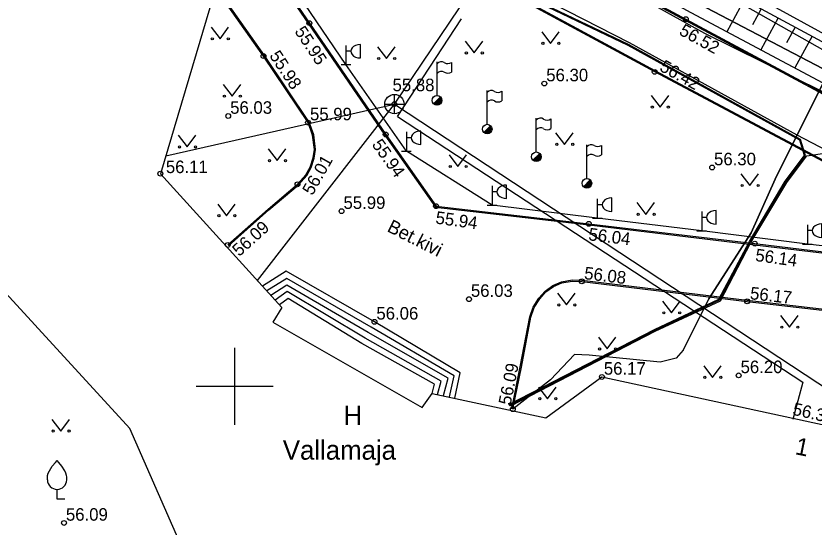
# Model space of a CAD drawing. Extents: x 542320 to 543602, y 6558748 to 6559969.
# Drawn here: x 543038.66 to 543080.07, y 6558892.7 to 6558919.22 of the extents above; entities that cross this region are included whole.
import ezdxf

# ---------------------------------------------------------------- set-up
doc = ezdxf.new("R2010")
doc.units = 0
for name, color, linetype in [('HALJASTUS', 7, 'Continuous'), ('HOONE', 7, 'Continuous'), ('HOONEDET', 7, 'Continuous'), ('KKAEV', 7, 'Continuous'), ('KORGUS-EH2000', 7, 'Continuous'), ('KTRASS', 7, 'Continuous'), ('MPKAABEL', 7, 'Continuous'), ('MPOHULIIN', 7, 'Continuous'), ('PIIR', 7, 'Continuous'), ('POST', 7, 'Continuous'), ('PUU', 7, 'Continuous'), ('RAJATIS', 7, 'Continuous'), ('RELJEEF', 7, 'Continuous'), ('SITRASS', 7, 'Continuous'), ('TEE', 7, 'Continuous'), ('VORK', 7, 'Continuous'), ('VTRASS', 7, 'Continuous')]:
    doc.layers.add(name, color=color, linetype=linetype)

# ---------------------------------------------------------------- blocks, each defined once
blk = doc.blocks.new('VKORIS')
for p, q in [((0, 4), (0, -4)), ((-4, 0), (4, 0))]:
    blk.add_line(p, q)
blk = doc.blocks.new('KAABVA')
for p, q in [((0, 2), (0, 0)), ((1.5, 0.693), (1.5, 2.093))]:
    blk.add_line(p, q)
for points in [[(0.5, 1.393), (0, 1.393)], [(-0.5, 0), (0.5, 0)]]:
    blk.add_lwpolyline(points)
blk.add_ellipse((1.5, 1.393), major_axis=(1, 0), ratio=0.7, start_param=1.570796, end_param=4.712389)
blk = doc.blocks.new('PLPOST')
blk.add_line((-0.354, -0.353), (0.353, 0.354))
blk.add_circle((0, 0), 0.5)
for radius, start, end in [(0.45, 224.85406, 45.03563), (0.4, 224.84272, 45.04698), (0.35, 224.82813, 45.06157), (0.3, 224.80867, 45.08103), (0.25, 224.78144, 45.10826), (0.2, 224.74058, 45.14911), (0.15, 224.67249, 45.2172), (0.1, 224.53632, 45.35338), (0.05, 224.12776, 45.76193)]:
    blk.add_arc((0, 0), radius, start, end)
blk = doc.blocks.new('LIPP')
for p, q in [((0, 0.5), (0, 4)), ((1.506, 3.938), (1.506, 2.938))]:
    blk.add_line(p, q)
for centre, radius, start, end in [((0.446, 3.431), 0.576, 57.89407, 140.73656), ((1.114, 4.496), 0.682, 237.89407, 305.02189), ((0.446, 2.431), 0.576, 57.89407, 140.73656), ((1.114, 3.496), 0.682, 237.89407, 305.02189)]:
    blk.add_arc(centre, radius, start, end)
blk = doc.blocks.new('KAKAEV')
for p, q in [((0, -1), (0, 1)), ((-1, 0), (1, 0))]:
    blk.add_line(p, q)
blk.add_circle((0, 0), 1)
blk = doc.blocks.new('MURU')
for p, q in [((-0.927, 1.213), (0, 0)), ((0, 0), (0.891, 1.213))]:
    blk.add_line(p, q)
for centre in [(-0.802, 0), (0.856, 0)]:
    blk.add_circle(centre, 0.11)
blk = doc.blocks.new('RING02')
blk.add_circle((0, 0), 0.25)
blk = doc.blocks.new('VILJA1')
for p, q in [((0, 0), (0, 1)), ((0.8, 0), (0, 0))]:
    blk.add_line(p, q)
for points in [[(-1, 2), (-1, 2.3), (-0.98, 2.43), (-0.91, 2.69), (-0.79, 2.93), (-0.5, 3.4), (-0.18, 3.81), (0, 4)], [(1, 2), (1, 2.3), (0.98, 2.43), (0.91, 2.69), (0.79, 2.93), (0.5, 3.4), (0.18, 3.81), (0, 4)]]:
    blk.add_lwpolyline(points)
blk.add_arc((0, 2), 1, 180, 0)

msp = doc.modelspace()

# ---------------------------------------------------------------- linework, layer by layer
at = {"layer": 'HOONE'}
msp.add_lwpolyline([(543034.683, 6558908.573), (543039.145, 6558923.204), (543048.898, 6558920.298), (543046.148, 6558911.034), (543052.456, 6558904.09), (543051.993, 6558903.334), (543059.743, 6558898.897), (543060.252, 6558899.636), (543066.159, 6558898.365), (543069.065, 6558900.487), (543081.93, 6558897.713), (543079.788, 6558887.775), (543071.384, 6558889.615), (543068.481, 6558887.445), (543058.412, 6558889.575), (543048.599, 6558888.632), (543044.558, 6558897.817)], close=True, dxfattribs=at)
at = {"layer": 'HOONEDET'}
for points in [[(543061.428, 6558899.383), (543061.705, 6558900.698), (543057.26, 6558903.347), (543052.674, 6558905.983), (543051.446, 6558905.202)], [(543061.158, 6558899.446), (543061.396, 6558900.537), (543057.097, 6558903.067), (543052.709, 6558905.6), (543051.668, 6558904.958)], [(543060.843, 6558899.519), (543061.082, 6558900.415), (543056.933, 6558902.787), (543052.712, 6558905.253), (543051.888, 6558904.716)], [(543060.537, 6558899.577), (543060.727, 6558900.266), (543056.77, 6558902.507), (543052.727, 6558904.925), (543052.104, 6558904.478)], [(543060.252, 6558899.636), (543060.381, 6558900.116), (543056.607, 6558902.227), (543052.787, 6558904.55), (543052.326, 6558904.233)]]:
    msp.add_lwpolyline(points, dxfattribs=at)
at = {"layer": 'KTRASS'}
for points in [[(543046.435, 6558911.953), (543058.296, 6558914.646), (543066.44, 6558926.74)], [(543051.198, 6558905.487), (543058.296, 6558914.646), (543080.977, 6558899.722)]]:
    msp.add_lwpolyline(points, dxfattribs=at)
at = {"layer": 'MPKAABEL'}
msp.add_lwpolyline([(543081.761, 6558896.926), (543082.099, 6558896.873), (543082.395, 6558897.034), (543085.057, 6558906.769), (543079.727, 6558907.382), (543074.242, 6558908.071), (543068.825, 6558908.727), (543063.367, 6558909.397), (543058.921, 6558912.202), (543055.778, 6558916.692), (543052.723, 6558921.189), (543049.567, 6558925.65)], dxfattribs=at)
at = {"layer": 'MPOHULIIN'}
msp.add_lwpolyline([(543099.403, 6558906.806), (543072.616, 6558921.947), (543045.501, 6558937.03), (543017.777, 6558952.769), (543011.701, 6558956.054)], dxfattribs=at)
at = {"layer": 'PIIR'}
for points in [[(543133.64, 6558888.72), (543040.58, 6558937.38), (543035.44, 6558940.39), (542997.88, 6558962.4), (542987.35, 6558968.48), (542985.46, 6558965.33), (542959.34, 6558980.79), (542961.33, 6558984.1), (542942.14, 6558992.15), (542929.74, 6558997.94), (542900.76, 6559010.27), (542901.6, 6559029.9)], [(543035.44, 6558940.39), (543040.58, 6558937.38), (543133.64, 6558888.72), (543159.27, 6558882.37), (543180.35, 6558877.33), (543188.6, 6558877.87), (543138.85, 6558855), (543136.39, 6558853.9), (543124.53, 6558851.31), (543111.21, 6558848.45), (543108.75, 6558866.73), (543082.72, 6558864.15), (543047.4, 6558848.41), (543054.87, 6558832.91), (543045.52, 6558829.45), (543026.29, 6558871.02), (543014.78, 6558890.86), (543006.52, 6558905.62), (543035.44, 6558940.39)]]:
    msp.add_lwpolyline(points, dxfattribs=at)
at = {"layer": 'RELJEEF'}
for points in [[(543101.897, 6558904.434), (543099.403, 6558906.806), (543096.044, 6558909.437), (543087.206, 6558914.268), (543074.649, 6558921.041), (543062.51, 6558927.7), (543050.982, 6558934.283), (543039.149, 6558941.077)], [(543037.968, 6558939.072), (543049.987, 6558932.338), (543073.674, 6558919.4), (543086.307, 6558912.668), (543095.539, 6558907.795), (543101.897, 6558904.434)], [(543076.451, 6558920.069), (543075.551, 6558918.4)], [(543077.332, 6558919.594), (543076.883, 6558918.762)], [(543078.212, 6558919.119), (543077.316, 6558917.459)], [(543079.092, 6558918.645), (543078.645, 6558917.817)], [(543079.972, 6558918.17), (543079.081, 6558916.519)]]:
    msp.add_lwpolyline(points, dxfattribs=at)
at = {"layer": 'SITRASS'}
for points in [[(543005.218, 6558957.454), (543044.997, 6558934.01), (543059.196, 6558926.752), (543074.381, 6558918.33), (543088.205, 6558911.502)], [(543064.26, 6558899.01), (543071.81, 6558902.91), (543075.17, 6558904.48), (543076.76, 6558907.49), (543078.62, 6558910.61), (543079.63, 6558911.97), (543079.37, 6558912.8), (543070.45, 6558917.73), (543064, 6558920.82), (543057.14, 6558924.93), (543052.25, 6558927.86), (543046.19, 6558930.99), (543042.46, 6558932.62), (543041.21, 6558933.18), (543040.24, 6558933.33), (543036.74, 6558935.74), (543033.41, 6558937.8), (543027.38, 6558941.25), (543021.13, 6558945), (543014.59, 6558948.63), (543009.37, 6558951.53), (543004.894, 6558954.068)], [(543064.24, 6558899.05), (543071.79, 6558902.95), (543075.13, 6558904.52), (543076.72, 6558907.51), (543078.58, 6558910.64), (543079.57, 6558911.98), (543079.33, 6558912.77), (543070.43, 6558917.69), (543063.98, 6558920.78), (543057.11, 6558924.89), (543052.23, 6558927.82), (543046.17, 6558930.94), (543042.44, 6558932.57), (543041.2, 6558933.13), (543040.22, 6558933.28), (543036.71, 6558935.7), (543033.38, 6558937.76), (543027.35, 6558941.21), (543021.1, 6558944.96), (543014.57, 6558948.59), (543009.35, 6558951.49), (543004.955, 6558953.977)], [(543121.901, 6558892.876), (543114.85, 6558896.99), (543111.27, 6558898.1), (543100.18, 6558902.69), (543091.12, 6558906.8), (543079.2, 6558913.04), (543070.5, 6558917.82), (543064.13, 6558921.1), (543057.19, 6558925.02), (543052.3, 6558927.95), (543046.23, 6558931.08), (543041.478, 6558932.313)], [(543150.381, 6558900.817), (543149.118, 6558899.488), (543147.687, 6558899.611), (543141.92, 6558901.373), (543128.068, 6558907.732), (543119.398, 6558911.928), (543114.519, 6558913.803), (543110.489, 6558914.465), (543105.407, 6558916.546), (543094.307, 6558922.284), (543086.864, 6558926.326), (543085.516, 6558925.687), (543081.664, 6558918.001), (543078.063, 6558910.75), (543076.812, 6558907.966), (543074.612, 6558904.543), (543073.274, 6558901.882), (543072.923, 6558901.455), (543072.094, 6558901.248), (543068.398, 6558901.619), (543067.64, 6558901.649), (543066.401, 6558900.344), (543064.442, 6558898.816)], [(543073.274, 6558901.882), (543074.612, 6558904.543), (543076.812, 6558907.966), (543078.063, 6558910.75), (543081.664, 6558918.001), (543085.516, 6558925.687)], [(543064.33, 6558898.99), (543071.83, 6558902.87), (543075.21, 6558904.44), (543076.8, 6558907.47), (543078.66, 6558910.58), (543079.69, 6558911.96), (543080.74, 6558912.11), (543085.83, 6558909.45), (543091.08, 6558906.71), (543100.42, 6558902.47), (543106.04, 6558900.15), (543110.07, 6558898.37), (543111.55, 6558895.04), (543112.38, 6558892.93), (543113.811, 6558888.962)]]:
    msp.add_lwpolyline(points, dxfattribs=at)
at = {"layer": 'TEE'}
for points in [[(543100.939, 6558907.078), (543096.605, 6558909.676), (543087.4, 6558914.549), (543074.818, 6558921.463), (543062.815, 6558928.334), (543051.193, 6558934.777), (543039.337, 6558941.411)], [(543037.628, 6558938.816), (543049.652, 6558932.038), (543061.266, 6558925.532), (543073.39, 6558918.997), (543086.032, 6558912.226), (543093.141, 6558908.472), (543101.872, 6558904.379), (543104.96, 6558903.002), (543104.998, 6558903.893), (543104.894, 6558904.285), (543104.476, 6558905.119), (543104.056, 6558905.544), (543103.371, 6558905.967), (543101.022, 6558907.105), (543101.348, 6558907.702)], [(543037.657, 6558938.868), (543049.681, 6558932.09), (543061.295, 6558925.585), (543073.418, 6558919.05), (543086.06, 6558912.279), (543093.168, 6558908.526), (543101.897, 6558904.434), (543104.904, 6558903.093), (543104.938, 6558903.886), (543104.838, 6558904.264), (543104.427, 6558905.084), (543104.018, 6558905.497), (543103.342, 6558905.914), (543100.939, 6558907.078), (543101.295, 6558907.731)], [(543042.737, 6558925.163), (543043.156, 6558929.286), (543043.417, 6558931.913), (543045.41, 6558930.807), (543047.371, 6558929.686), (543047.085, 6558929.65), (543046.647, 6558929.461), (543046.236, 6558929.178), (543045.927, 6558928.765), (543045.764, 6558928.283), (543045.654, 6558927.323), (543046.056, 6558926.337), (543046.056, 6558926.337), (543049.803, 6558924.792), (543053.881, 6558918.848), (543057.844, 6558913.069), (543060.456, 6558909.35), (543068.387, 6558908.432), (543076.995, 6558907.406), (543085.705, 6558906.357), (543091.424, 6558905.658), (543091.756, 6558905.73)], [(543042.797, 6558925.157), (543043.216, 6558929.28), (543043.468, 6558931.816), (543045.381, 6558930.755), (543047.185, 6558929.723), (543047.069, 6558929.708), (543046.618, 6558929.514), (543046.194, 6558929.222), (543045.873, 6558928.793), (543045.705, 6558928.296), (543045.593, 6558927.315), (543045.992, 6558926.336), (543045.997, 6558926.308), (543049.765, 6558924.741), (543053.832, 6558918.814), (543057.795, 6558913.035), (543060.422, 6558909.293), (543068.38, 6558908.372), (543076.988, 6558907.346), (543085.698, 6558906.297), (543091.427, 6558905.597), (543091.769, 6558905.671)], [(543100.579, 6558901.54), (543091.756, 6558905.73), (543084.794, 6558909.393), (543071.804, 6558916.315), (543060.017, 6558922.694), (543047.371, 6558929.686)], [(543100.605, 6558901.594), (543091.783, 6558905.784), (543084.822, 6558909.446), (543071.832, 6558916.368), (543060.046, 6558922.747), (543047.4, 6558929.739)], [(543049.646, 6558907.336), (543051.74, 6558909.197), (543053.266, 6558910.484), (543053.702, 6558910.97), (543053.925, 6558911.375), (543054.074, 6558911.85), (543054.14, 6558912.292), (543054.048, 6558913.041), (543053.814, 6558913.686), (543051.501, 6558917.137), (543046.742, 6558923.877)], [(543049.686, 6558907.291), (543051.779, 6558909.152), (543053.308, 6558910.441), (543053.751, 6558910.935), (543053.98, 6558911.351), (543054.133, 6558911.837), (543054.201, 6558912.291), (543054.107, 6558913.055), (543053.868, 6558913.713), (543051.55, 6558917.171), (543046.791, 6558923.912)], [(543064.383, 6558898.828), (543064.824, 6558901.004), (543065.315, 6558903.6), (543065.501, 6558904.114), (543065.786, 6558904.583), (543066.12, 6558904.945), (543066.513, 6558905.224), (543066.963, 6558905.429), (543067.522, 6558905.525), (543068.025, 6558905.508), (543076.608, 6558904.469), (543084.451, 6558903.561), (543083.588, 6558899.607)], [(543064.442, 6558898.816), (543064.883, 6558900.992), (543065.373, 6558903.584), (543065.555, 6558904.088), (543065.834, 6558904.547), (543066.16, 6558904.9), (543066.543, 6558905.172), (543066.981, 6558905.371), (543067.526, 6558905.465), (543068.02, 6558905.448), (543076.601, 6558904.409), (543084.378, 6558903.509), (543083.529, 6558899.62)]]:
    msp.add_lwpolyline(points, dxfattribs=at)
at = {"layer": 'VTRASS'}
for points in [[(543058.459, 6558914.004), (543061.769, 6558919.075)], [(543058.459, 6558914.004), (543079.485, 6558900.209), (543078.975, 6558898.28)]]:
    msp.add_lwpolyline(points, dxfattribs=at)

# ---------------------------------------------------------------- block references
at = {"layer": 'HALJASTUS', "xscale": 0.5, "yscale": 0.5}
for p in [(543049.246, 6558918.035), (543066.404, 6558917.796), (543062.43, 6558917.298), (543057.881, 6558917.015), (543049.874, 6558915.061), (543072.084, 6558914.491), (543047.545, 6558912.421), (543067.122, 6558912.556), (543052.215, 6558911.712), (543061.595, 6558911.403), (543076.741, 6558910.424), (543049.589, 6558908.854), (543071.344, 6558908.924), (543067.231, 6558904.22), (543072.675, 6558903.815), (543078.801, 6558903.068), (543069.345, 6558901.937), (543074.809, 6558900.465), (543066.242, 6558899.357), (543040.983, 6558897.68)]:
    msp.add_blockref('MURU', p, dxfattribs=at)
at = {"layer": 'KKAEV', "xscale": 0.5, "yscale": 0.5}
msp.add_blockref('KAKAEV', (543058.296, 6558914.646), dxfattribs=at)
at = {"layer": 'KORGUS-EH2000', "xscale": 0.5, "yscale": 0.5}
for p in [(543073.418, 6558919.05), (543053.881, 6558918.848), (543051.501, 6558917.137), (543071.804, 6558916.315), (543066.075, 6558915.711), (543058.296, 6558914.646), (543049.672, 6558914.026), (543053.814, 6558913.686), (543057.844, 6558913.069), (543074.782, 6558911.353), (543046.148, 6558911.034), (543053.266, 6558910.484), (543055.553, 6558909.088), (543060.456, 6558909.35), (543068.387, 6558908.432), (543076.995, 6558907.406), (543049.646, 6558907.336), (543068.02, 6558905.448), (543062.165, 6558904.525), (543076.601, 6558904.409), (543057.26, 6558903.347), (543069.065, 6558900.487), (543076.16, 6558900.567), (543064.442, 6558898.816), (543041.147, 6558892.91)]:
    msp.add_blockref('RING02', p, dxfattribs=at)
at = {"layer": 'POST', "xscale": 0.5, "yscale": 0.5}
for p in [(543055.778, 6558916.692), (543058.921, 6558912.202), (543063.367, 6558909.397), (543068.825, 6558908.727), (543074.242, 6558908.071), (543079.727, 6558907.382)]:
    msp.add_blockref('KAABVA', p, dxfattribs=at)
at = {"layer": 'PUU', "xscale": 0.5, "yscale": 0.5}
msp.add_blockref('VILJA1', (543040.79, 6558894.15), dxfattribs=at)
at = {"layer": 'RAJATIS', "xscale": 0.5, "yscale": 0.5}
for name, p in [('LIPP', (543060.506, 6558914.84)), ('LIPP', (543063.112, 6558913.347)), ('PLPOST', (543060.506, 6558914.84)), ('LIPP', (543065.659, 6558911.911)), ('PLPOST', (543063.112, 6558913.347)), ('LIPP', (543068.284, 6558910.535)), ('PLPOST', (543065.659, 6558911.911)), ('PLPOST', (543068.284, 6558910.535))]:
    msp.add_blockref(name, p, dxfattribs=at)
at = {"layer": 'VORK', "xscale": 0.5, "yscale": 0.5}
msp.add_blockref('VKORIS', (543050, 6558900), dxfattribs=at)

# ---------------------------------------------------------------- texts
at = {"layer": 'HOONE'}
for s, p in [('H', (543055.658, 6558897.988)), ('Vallamaja', (543052.505, 6558896.193))]:
    msp.add_text(s, height=1, dxfattribs=at).set_placement(p)
msp.add_text('1', height=0.9, rotation=348.5779, dxfattribs=at).set_placement((543079.049, 6558896.483))
at = {"layer": 'KORGUS-EH2000'}
for s, rotation, p in [('55.95', 303.717, (543053.088, 6558918.418)), ('56.52', 331.0431, (543073.024, 6558918.276)), ('55.98', 303.3659, (543051.782, 6558917.156)), ('56.42', 331.0431, (543072.009, 6558916.405)), ('55.94', 305.4472, (543057.098, 6558912.541)), ('56.01', 60.1159, (543054.038, 6558909.868)), ('55.94', 352.0694, (543060.403, 6558908.449)), ('56.09', 41.8283, (543050.238, 6558906.707)), ('56.04', 353.0458, (543068.341, 6558907.583)), ('56.14', 352.1498, (543076.996, 6558906.505)), ('56.08', 353.1543, (543068.118, 6558905.565)), ('56.17', 353.4735, (543076.726, 6558904.524)), ('56.09', 78.6824, (543064.325, 6558898.993)), ('56.30', 347.0283, (543078.92, 6558898.533))]:
    msp.add_text(s, height=0.65, rotation=rotation, dxfattribs=at).set_placement(p)
for s, p in [('56.30', (543066.175, 6558915.828)), ('55.88', (543058.199, 6558915.314)), ('56.03', (543049.772, 6558914.143)), ('55.99', (543053.914, 6558913.803)), ('56.30', (543074.882, 6558911.47)), ('56.11', (543046.435, 6558911.065)), ('55.99', (543055.653, 6558909.205)), ('56.03', (543062.265, 6558904.642)), ('56.06', (543057.36, 6558903.464)), ('56.20', (543076.26, 6558900.684)), ('56.17', (543069.165, 6558900.604)), ('56.09', (543041.247, 6558893.027))]:
    msp.add_text(s, height=0.65, dxfattribs=at).set_placement(p)
at = {"layer": 'TEE'}
msp.add_text('Bet.kivi', height=0.7, rotation=333.1699, dxfattribs=at).set_placement((543057.867, 6558908.062))

doc.saveas('drawing.dxf')
